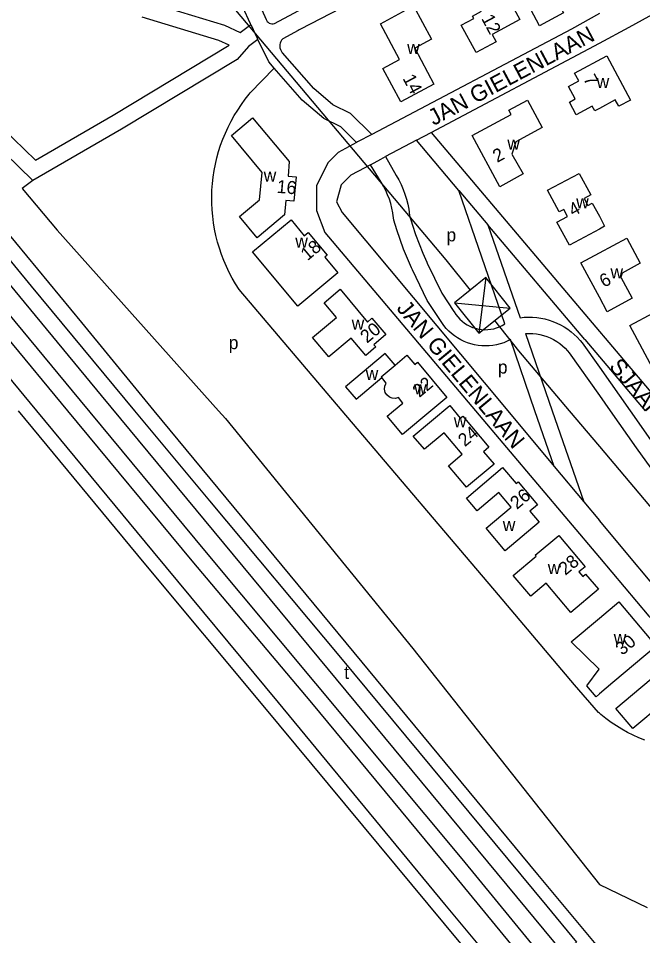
# Model space of a CAD drawing. Extents: x 156721 to 158827, y 386657 to 388950.
# Drawn here: x 157871.8 to 158063.3, y 386821.6 to 387103.3 of the extents above; entities that cross this region are included whole.
import ezdxf

# ---------------------------------------------------------------- set-up
doc = ezdxf.new("R2010")
doc.units = 0
for name, color, linetype in [('BLT_Basislijn', 7, 'Continuous'), ('BLT_Bebouwing', 7, 'Continuous'), ('BLT_Centroide', 7, 'Continuous'), ('BLT_Hoogspanningsmast_en_leidingen', 7, 'Continuous'), ('BLT_Huisnummer', 7, 'Continuous'), ('BLT_Onderverdeling_panden', 7, 'Continuous'), ('BLT_Spoorlijn', 7, 'Continuous'), ('BLT_Straatnaam', 7, 'Continuous')]:
    doc.layers.add(name, color=color, linetype=linetype)

msp = doc.modelspace()

# ---------------------------------------------------------------- linework, layer by layer
at = {"layer": 'BLT_Basislijn'}
for p, q in [((157943.04, 387101.36), (157945.17, 387097.04)), ((157957.56, 387099.6), (157952.85, 387096.99)), ((157957.92, 387099.8), (157957.56, 387099.6)), ((157945.28, 387096.8), (157945.17, 387097.04)), ((157998.41, 387068.24), (158050, 387095.68)), ((157993.89, 387065.84), (157998.41, 387068.24)), ((157998.41, 387068.24), (158050, 387007.12)), ((157979.78, 387058.33), (157982.96, 387060.02)), ((157982.96, 387060.02), (157984.43, 387060.81)), ((158006.88, 387050.46), (158015.83, 387039.85)), ((158027.35, 387006.49), (158035.55, 386982.75)), ((158050, 387007.12), (158051.76, 387005.04)), ((158044.73, 387003.6), (158050, 386996.13)), ((158045.51, 387004.69), (158050, 386999.37)), ((158051.76, 387005.04), (158070.57, 386982.75)), ((158040.79, 387000.53), (158050, 386987.42)), ((158050, 386999.37), (158064.02, 386982.75)), ((158050, 386996.13), (158059.44, 386982.75)), ((158050, 386987.42), (158053.28, 386982.75)), ((158012.02, 386982.75), (158050, 386937.71)), ((158035.55, 386982.75), (158045.2, 386954.82)), ((158053.28, 386982.75), (158061.27, 386971.39)), ((158059.44, 386982.75), (158066.41, 386972.87)), ((158061.27, 386971.39), (158071.07, 386957.77)), ((158036.17, 386965.65), (158045.2, 386954.82)), ((158045.2, 386954.82), (158050, 386949.07)), ((157992.83, 386909.79), (158050, 386837.24)), ((158050, 386889.86), (158049.73, 386890.09))]:
    msp.add_line(p, q, dxfattribs=at)
for points in [[(157648.04, 387289.7), (157544.83, 387414.91), (157472.21, 387499.44), (157437.72, 387541.12), (157436.87, 387543.75), (157439.78, 387545.45), (157442.04, 387545.5), (157456.85, 387528.49), (157499.46, 387477.15), (157606.86, 387347.11), (157687.66, 387250), (157720.52, 387210.5), (157729.65, 387199.36), (157875.7, 387021.05), (157907.43, 386982.75), (157930.36, 386955.08), (157970.6, 386906.98), (158033.86, 386830.67), (158043.03, 386819.55)], [(158064.67, 386799.98), (158050, 386817.63), (158031.12, 386840.35), (157972.29, 386911.55), (157913.47, 386982.75), (157908.84, 386988.36), (157891.22, 387009.92), (157816.86, 387100), (157729.65, 387207.88), (157695.61, 387250), (157574.66, 387396.74), (157506.93, 387478.89), (157495.28, 387493.01), (157484.63, 387513.61), (157485.73, 387516.66)], [(157648.04, 387289.7), (157718.27, 387204.49), (157897.14, 386987.42), (158038.9, 386816.21), (158043.03, 386819.55)], [(158050, 387149.11), (158004.45, 387123.88), (157958.31, 387100), (157957.92, 387099.8)], [(157911.15, 387146.08), (157907.63, 387143.41), (157907.16, 387136.63), (157907.44, 387132.99), (157907.97, 387131.05), (157907.69, 387128.52), (157906.49, 387126.83), (157904.92, 387124.92), (157902.95, 387123.09), (157901.99, 387121.78), (157901.55, 387120.79), (157901.55, 387119.37), (157901.75, 387118.27), (157902.53, 387116.81), (157904.69, 387114.22), (157906.87, 387111.72), (157908.2, 387110.12), (157909.88, 387109.04), (157911.43, 387108.4), (157935.01, 387101.21), (157939.83, 387098.99), (157943.04, 387101.36)], [(157943.04, 387101.36), (157942.93, 387101.58), (157940.65, 387106.75), (157937.08, 387113.01), (157932.28, 387119.01), (157924.61, 387127.31), (157911.15, 387146.08)], [(157945.12, 387109.01), (157947.79, 387102.9), (157947.88, 387102.71), (157948.11, 387102.36), (157948.4, 387102.07), (157948.75, 387101.84), (157949.13, 387101.68), (157949.53, 387101.59), (157949.95, 387101.59), (157950.35, 387101.66), (157987.22, 387121.57)], [(157824.9, 387118.85), (157857.15, 387081.13), (157866.89, 387069.53), (157876.98, 387059.71), (157900.89, 387073.56), (157936.44, 387095.05), (157933.23, 387096.52), (157909.73, 387103.69)], [(157821.05, 387115.66), (157853.32, 387077.91), (157863.23, 387066.12), (157876.21, 387053.49)], [(158059.17, 387100.59), (158073.42, 387108.51), (158075.59, 387108.08), (158086.03, 387100), (158100.88, 387087.28), (158108.78, 387077.04), (158124.86, 387046.62), (158147.37, 387001.57), (158156.07, 386982.75)], [(158050, 387104.8), (158041.5, 387100), (157980.16, 387067.66)], [(158050, 387095.68), (158059.17, 387100.59)], [(157945.28, 387096.8), (157942.37, 387094.66), (157938.86, 387090.67), (157903.44, 387069.26), (157876.21, 387053.49)], [(157950.23, 387088.01), (157948.58, 387089.89), (157945.28, 387096.8)], [(157952.85, 387096.99), (157952.53, 387096.6), (157952.27, 387096.17), (157952.09, 387095.7), (157951.99, 387095.21), (157951.96, 387094.71), (157952.01, 387094.21), (157952.15, 387093.73), (157952.35, 387093.27), (157952.63, 387092.85), (157952.79, 387092.66)], [(157980.16, 387067.66), (157973.62, 387074.05), (157968.25, 387076.73), (157962.4, 387081.71), (157952.79, 387092.66)], [(158019.06, 386926.2), (157971.1, 386982.75), (157939.49, 387020.02), (157938.41, 387021.72), (157937.4, 387023.46), (157936.47, 387025.23), (157935.6, 387027.05), (157934.81, 387028.89), (157934.09, 387030.77), (157933.44, 387032.67), (157932.87, 387034.6), (157932.38, 387036.55), (157931.97, 387038.52), (157931.64, 387040.5), (157931.38, 387042.49), (157931.2, 387044.5), (157931.11, 387046.51), (157931.09, 387048.52), (157931.15, 387050.52), (157931.3, 387052.53), (157931.52, 387054.53), (157931.83, 387056.51), (157932.21, 387058.49), (157932.67, 387060.45), (157933.2, 387062.38), (157933.82, 387064.3), (157934.51, 387066.18), (157935.27, 387068.04), (157936.11, 387069.87), (157937.02, 387071.66), (157938, 387073.42), (157939.05, 387075.13), (157940.17, 387076.8), (157941.35, 387078.43), (157942.59, 387080.01), (157942.91, 387080.39), (157950.23, 387088.01)], [(157975.52, 387065.21), (157970.68, 387069.93), (157965.47, 387072.53), (157958.88, 387078.14), (157950.23, 387088.01)], [(157814.87, 387077.69), (157890.73, 386985.94), (157928.85, 386939.83)], [(157980.16, 387067.66), (157975.76, 387065.34), (157975.52, 387065.21)], [(157975.52, 387065.21), (157969.91, 387062.12), (157966.7, 387058.91), (157963.19, 387051.89), (157963.19, 387044.28), (157965.82, 387037.55), (158012.02, 386982.75)], [(157993.89, 387065.84), (157984.43, 387060.81)], [(158006.88, 387050.46), (157993.89, 387065.84)], [(157984.43, 387060.81), (157987.69, 387055.04), (157988.46, 387053.66), (157989.16, 387052.23), (157989.79, 387050.77), (157990.34, 387049.28), (157990.82, 387047.77), (157991.22, 387046.23), (157991.55, 387044.67), (157991.71, 387042.71), (157992.63, 387039.8), (157993.62, 387036.91), (157994.69, 387034.04), (157995.84, 387031.21), (157997.05, 387028.4), (157997.2, 387028.08), (158001.69, 387018.88), (158005.41, 387013.26), (158005.47, 387013.16), (158005.98, 387012.37), (158006.55, 387011.62), (158007.19, 387010.93), (158007.88, 387010.29), (158008.63, 387009.71), (158009.42, 387009.2), (158010.25, 387008.76), (158011.11, 387008.39), (158012.01, 387008.09), (158012.92, 387007.87), (158013.85, 387007.73), (158014.79, 387007.67), (158015.74, 387007.69), (158016.67, 387007.79), (158017.6, 387007.97), (158018.5, 387008.23), (158019.38, 387008.56), (158020.23, 387008.96), (158021.04, 387009.44), (158006.88, 387050.46)], [(157979.78, 387058.33), (157978.04, 387057.41), (157973.71, 387055.1), (157970.79, 387052.18), (157969.33, 387046.91), (157971.08, 387043.69), (158021.91, 386982.75), (158036.17, 386965.65)], [(158036.17, 386965.65), (158030.26, 386982.75), (158022.71, 387004.62), (158021.7, 387004.11), (158020.65, 387003.68), (158019.57, 387003.32), (158018.47, 387003.04), (158017.36, 387002.84), (158016.23, 387002.72), (158015.1, 387002.67), (158013.96, 387002.71), (158012.83, 387002.82), (158011.72, 387003.02), (158010.62, 387003.29), (158009.54, 387003.64), (158008.49, 387004.07), (158007.47, 387004.56), (158006.49, 387005.13), (158005.55, 387005.77), (158004.65, 387006.47), (158003.82, 387007.23), (158003.03, 387008.05), (158002.31, 387008.93), (158001.65, 387009.85), (158001.07, 387010.78), (157997.18, 387016.62), (157992.64, 387026.02), (157992.36, 387026.65), (157991.12, 387029.52), (157989.96, 387032.42), (157988.87, 387035.34), (157987.86, 387038.3), (157986.93, 387041.28), (157986.69, 387043.43), (157986.67, 387043.54), (157986.38, 387044.97), (157986.02, 387046.38), (157985.58, 387047.77), (157985.06, 387049.13), (157984.47, 387050.46), (157983.8, 387051.76), (157983.07, 387053.02), (157979.78, 387058.33)], [(157876.21, 387053.49), (157872.9, 387051.05), (157883.66, 387038.24), (157933.18, 386982.75), (157935.29, 386980.39), (157992.83, 386909.79)], [(158015.83, 387039.85), (158025.68, 387011.34), (158026.95, 387011.48), (158028.24, 387011.53), (158029.52, 387011.51), (158030.8, 387011.41), (158032.07, 387011.22), (158033.32, 387010.96), (158034.56, 387010.62), (158035.77, 387010.21), (158036.96, 387009.72), (158038.11, 387009.15), (158039.22, 387008.52), (158040.3, 387007.81), (158041.32, 387007.05), (158042.3, 387006.22), (158043.22, 387005.33), (158044.09, 387004.38), (158044.73, 387003.6)], [(158045.51, 387004.69), (158015.83, 387039.85)], [(158027.35, 387006.49), (158028.47, 387006.53), (158029.58, 387006.49), (158030.69, 387006.38), (158031.79, 387006.18), (158032.87, 387005.91), (158033.93, 387005.55), (158034.96, 387005.13), (158035.96, 387004.63), (158036.92, 387004.06), (158037.84, 387003.42), (158038.71, 387002.72), (158039.52, 387001.96), (158040.28, 387001.14), (158040.79, 387000.53)], [(158089.5, 386921.13), (158088.31, 386920.54), (158082.76, 386918.2), (158077.2, 386918.2), (158074.28, 386919.96), (158050, 386949.07)], [(157928.85, 386939.83), (158007.82, 386845.12), (158053.87, 386788.96)], [(158050, 386937.71), (158065.22, 386919.66), (158070.77, 386913.52)], [(158049.73, 386890.09), (158042.42, 386898.65), (158019.06, 386926.2)], [(158063.97, 386881.57), (158062.15, 386882.31), (158060.37, 386883.12), (158058.62, 386884), (158056.91, 386884.96), (158055.23, 386885.98), (158053.61, 386887.08), (158052.02, 386888.23), (158050.49, 386889.45), (158050, 386889.86)], [(158050, 386837.24), (158064.71, 386830.24)]]:
    msp.add_lwpolyline(points, dxfattribs=at)
at = {"layer": 'BLT_Bebouwing'}
msp.add_line((157987.38, 386996.79), (157990.99, 386999.82), dxfattribs=at)
for points in [[(158038.85, 387131.08), (158043.15, 387123.04), (158039.83, 387121.25), (158045.72, 387110.3), (158038.33, 387106.33), (158039.05, 387105), (158031.66, 387101.02), (158029.01, 387105.96), (158029.76, 387106.36), (158027.96, 387109.71), (158032.24, 387112.01), (158033, 387114.18), (158031.37, 387117.35), (158034.22, 387118.82), (158030.82, 387125.13), (158031.51, 387127.1), (158038.85, 387131.08)], [(158017.58, 387115.05), (158020.76, 387109.16), (158021.93, 387109.79), (158025.65, 387102.91), (158017.11, 387098.32), (158018.3, 387096.11), (158012.17, 387092.82), (158007.65, 387101.17), (158011.48, 387103.22), (158011.07, 387103.98), (158013.82, 387105.45), (158011.07, 387110.57), (158014.02, 387112.15), (158013.61, 387112.92), (158017.58, 387115.05)], [(157993.02, 387107.11), (157998.49, 387096.91), (157993.35, 387094.16), (157999.25, 387083.12), (157989.07, 387077.67), (157983.61, 387087.86), (157988.73, 387090.6), (157982.82, 387101.65), (157993.02, 387107.11)], [(158050, 387075.6), (158048.6, 387074.85), (158047.82, 387076.29), (158042.89, 387073.69), (158040.8, 387077.56), (158042.58, 387078.53), (158040.49, 387082.4), (158043.68, 387084.07), (158042.41, 387086.48), (158052.28, 387091.76)], [(158052.28, 387091.76), (158059.56, 387078.21), (158055.97, 387076.29), (158054.89, 387078.25), (158050, 387075.6)], [(158028.01, 387078.17), (158032.5, 387069.77), (158024.34, 387065.41), (158023.17, 387061.59), (158026.62, 387055.53), (158019.46, 387051.57), (158011.02, 387067.34), (158022.91, 387073.72), (158022.2, 387075.05), (158028.01, 387078.17)], [(157943.6, 387072.73), (157954.86, 387059.33), (157954.5, 387054.87), (157956.95, 387054.64), (157956.32, 387047.18), (157953.85, 387047.38), (157953.44, 387042.97), (157945.03, 387035.91), (157939.59, 387042.45), (157945.77, 387047.6), (157946.53, 387055.96), (157937.11, 387067.27), (157943.6, 387072.73)], [(158050, 387038.58), (158040.81, 387033.63), (158037.01, 387040.68), (158040.26, 387042.44), (158039.09, 387044.62), (158037.7, 387043.87), (158034.14, 387050.48), (158043.8, 387055.68), (158047.36, 387049.08), (158045.33, 387047.98), (158046.52, 387045.78), (158047.85, 387046.49), (158050, 387042.49)], [(158050, 387042.49), (158051.63, 387039.46), (158050, 387038.58)], [(157955.45, 387041.38), (157959.47, 387036.53), (157960.71, 387037.57), (157966.52, 387030.56), (157965.8, 387029.96), (157969.81, 387025.11), (157957.53, 387014.94), (157943.62, 387031.58), (157955.45, 387041.38)], [(158050, 387031.23), (158058.41, 387035.75), (158062.54, 387028.05), (158056.96, 387024.99), (158056.61, 387023.8), (158060.08, 387017.36), (158052.37, 387013.2), (158050, 387017.61)], [(158050, 387017.61), (158044.31, 387028.18), (158050, 387031.23)], [(158073.92, 387016.78), (158075.04, 387014.7), (158075.64, 387015.02), (158077.82, 387010.95), (158073.77, 387008.77), (158073.38, 387009.48), (158070.81, 387008.09), (158071.43, 387006.93), (158070.52, 387003.96), (158069.5, 387003.41), (158072.72, 386997.36), (158067.17, 386994.4), (158059.34, 387008.93), (158073.92, 387016.78)], [(157987.38, 386996.79), (157984.34, 387000.36), (157972.14, 386990.17), (157975.36, 386986.31), (157983.23, 386992.94)], [(157990.99, 386999.82), (157993.4, 386996.98), (157994.21, 386997.67), (158003.26, 386986.88), (157998.32, 386982.75)], [(157986.9, 386982.75), (157989.74, 386985.14), (157988.37, 386986.83), (157987.44, 386986.56), (157986.48, 386986.61), (157985.58, 386986.96), (157984.81, 386987.62), (157984.32, 386988.43), (157984.11, 386989.36), (157984.22, 386990.35), (157984.65, 386991.26), (157983.23, 386992.94)], [(157998.32, 386982.75), (157989.66, 386975.51), (157984.94, 386981.11), (157986.9, 386982.75)], [(158020.34, 386965.31), (158024.47, 386960.41), (158025.06, 386960.91), (158031.01, 386953.86), (158028.68, 386951.9), (158031.5, 386948.56), (158021.08, 386939.78), (158015.27, 386946.67), (158022.95, 386953.14), (158019.16, 386957.64), (158012.53, 386952.05), (158009.24, 386955.96), (158020.34, 386965.31)], [(158037.58, 386944.45), (158045.62, 386934.87), (158044.62, 386934.03), (158043.73, 386933.29), (158044.89, 386931.9), (158045.78, 386932.64), (158049.72, 386927.95), (158041.21, 386920.81), (158033.68, 386929.79), (158028.94, 386925.82), (158023.58, 386932.2), (158030.62, 386938.09), (158030.35, 386938.42), (158037.58, 386944.45)], [(158050, 386919.08), (158055.98, 386924.11), (158067.46, 386910.44), (158054.18, 386899.32), (158050, 386895.81)], [(158050, 386895.81), (158048.99, 386894.96), (158046.17, 386898.33), (158049.98, 386903.41), (158041.35, 386911.8), (158050, 386919.08)], [(158069.59, 386892.99), (158060.32, 386885.17), (158055.09, 386891.3), (158071, 386904.73)]]:
    msp.add_lwpolyline(points, dxfattribs=at)
for points in [[(157965.55, 387015.97), (157970.47, 387020.08), (157978.87, 387010.03), (157980.25, 387011.19), (157984.48, 387006.15), (157980.81, 387003.05), (157981.39, 387002.36), (157978.32, 386999.79), (157973.87, 387005.05), (157966.99, 386999.29), (157961.96, 387005.29), (157969.33, 387011.45)], [(157992.93, 386974.99), (158004.11, 386984.34), (158007.32, 386980.51), (158008.08, 386981.15), (158016.12, 386971.58), (158014.48, 386970.19), (158017.71, 386966.35), (158009.2, 386959.27), (158003.68, 386965.86), (158007.92, 386969.43), (158002.41, 386976), (157996.36, 386970.93)]]:
    msp.add_lwpolyline(points, close=True, dxfattribs=at)
at = {"layer": 'BLT_Hoogspanningsmast_en_leidingen'}
for p, q in [((157871.77, 387184.94), (158002.9, 387029.14)), ((158002.9, 387029.14), (158010.34, 387019.81)), ((158015.15, 387023.65), (158005.53, 387015.97)), ((158015.15, 387023.65), (158012.98, 387006.64)), ((158022.6, 387014.32), (158015.15, 387023.65)), ((158005.53, 387015.97), (158012.98, 387006.64)), ((158005.53, 387015.97), (158022.6, 387014.32)), ((158012.98, 387006.64), (158022.6, 387014.32)), ((158017.79, 387010.48), (158025.23, 387001.15)), ((158025.23, 387001.15), (158040.73, 386982.75)), ((158040.73, 386982.75), (158050, 386971.75)), ((158050, 386971.75), (158156.64, 386845.18))]:
    msp.add_line(p, q, dxfattribs=at)
at = {"layer": 'BLT_Onderverdeling_panden'}
msp.add_lwpolyline([(157983.23, 386992.94), (157983.05, 386993.16), (157987.38, 386996.79)], dxfattribs=at)
at = {"layer": 'BLT_Spoorlijn'}
for points in [[(157800.68, 387075.45), (157877.31, 386982.75)], [(157811.02, 387074.51), (157886.87, 386982.75)], [(157871.75, 386982.75), (157910.28, 386936.02)], [(157877.31, 386982.75), (157913.1, 386939.46)], [(157886.87, 386982.75), (157924.99, 386936.64)], [(157913.1, 386939.46), (157951.5, 386893.19)], [(157910.28, 386936.02), (157946.8, 386892.25)], [(157924.99, 386936.64), (157961.67, 386893.03)], [(157951.5, 386893.19), (158002.54, 386831.29)], [(157961.67, 386893.03), (158003.95, 386841.95)], [(157946.8, 386892.25), (158002.39, 386825.18)], [(158003.95, 386841.95), (158050, 386785.79)], [(158002.54, 386831.29), (158050, 386774.11)], [(158002.39, 386825.18), (158050, 386767.73)]]:
    msp.add_lwpolyline(points, dxfattribs=at)

# ---------------------------------------------------------------- texts
at = {"layer": 'BLT_Centroide'}
for s, p in [('w', (157991.03, 387092.38)), ('w', (158049.18, 387081.88)), ('w', (158021.77, 387062.97)), ('w', (157947.03, 387053.12)), ('w', (158042.89, 387044.97)), ('p', (158003.1, 387034.8)), ('w', (157956.72, 387032.86)), ('w', (158053.42, 387023.42)), ('w', (157974.02, 387007.66)), ('p', (157936.31, 387001.69)), ('p', (158018.87, 386994.2)), ('w', (157978.33, 386992.21)), ('w', (157993.16, 386987.86)), ('w', (158005.36, 386977.66)), ('w', (158020.38, 386945.8)), ('w', (158034.19, 386932.62)), ('w', (158054.41, 386911.14)), ('t', (157971.72, 386900.43))]:
    msp.add_text(s, height=4, dxfattribs=at).set_placement(p)
at = {"layer": 'BLT_Huisnummer'}
for s, rotation, p in [('12', 298.1581, (158013.69, 387103.25)), ('14', 298.1581, (157989.55, 387084.86)), ('7', 298.5493, (158044.95, 387084.73)), ('2', 28.9777, (158018.68, 387058.88)), ('16', 355.2632, (157950.94, 387049.72)), ('4', 28.3201, (158041.92, 387042.34)), ('18', 39.6266, (157960.44, 387028.67)), ('6', 28.3552, (158051.4, 387020.5)), ('20', 39.8882, (157978.72, 387003.35)), ('22', 39.8821, (157994.78, 386986.66)), ('24', 39.8929, (158008.72, 386971.53)), ('26', 40.1102, (158024.72, 386952.3)), ('28', 40.007, (158039.57, 386932.04)), ('30', 39.9669, (158057.04, 386907.48))]:
    msp.add_text(s, height=4, rotation=rotation, dxfattribs=at).set_placement(p)
at = {"layer": 'BLT_Straatnaam'}
for s, height, rotation, p in [('JAN GIELENLAAN', 5, 28.0101, (157999.16, 387070.21)), ('JAN GIELENLAAN', 4.9999, 309.7045, (157987.57, 387014.13)), ('SJAAK KRUIJSSENLAAN', 5, 310.1772, (158052.75, 386996.22))]:
    msp.add_text(s, height=height, rotation=rotation, dxfattribs=at).set_placement(p)

doc.saveas('drawing.dxf')
